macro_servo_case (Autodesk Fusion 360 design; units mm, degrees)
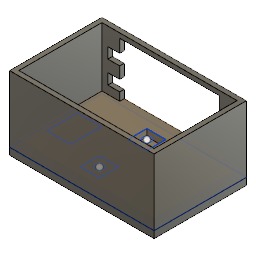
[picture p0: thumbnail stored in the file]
sketch "Sketch1" plane through (0, 0, 0) normal (0, 1, 0) x axis (1, 0, 0)
  line L1 (36.1323, 27.0695) -> (-24.8677, 27.0695)
  line L2 (36.1323, -11.9305) -> (36.1323, 27.0695)
  line L3 (-24.8677, -11.9305) -> (36.1323, -11.9305)
  line L4 (-24.8677, 27.0695) -> (-24.8677, -11.9305)
  point P2 (-24.8677, 27.0695)
  point P3 (36.1323, 27.0695)
  point P5 (-24.8677, -11.9305)
  dimension "d1" distance P2 P3 = 61
  dimension "d2" distance P2 P5 = 39
extrude "Extrude3" new body sketch "Sketch1" against normal blind 3
extrude "Extrude1" new body sketch "Sketch1" along normal blind 28
sketch "Sketch2" plane through (0, 28, 0) normal (0, 1, 0) x axis (-1, 0, 0)
  line L1 (-36.1323, 11.9305) -> (24.8677, 11.9305)
  line L2 (-36.1323, -27.0695) -> (-36.1323, 11.9305)
  line L3 (24.8677, -27.0695) -> (-36.1323, -27.0695)
  line L4 (24.8677, 11.9305) -> (24.8677, -27.0695)
  line L5 (-34.1323, -25.0695) -> (22.8677, -25.0695)
  line L6 (-34.1323, 9.9305) -> (-34.1323, -25.0695)
  line L7 (22.8677, 9.9305) -> (-34.1323, 9.9305)
  line L8 (22.8677, -25.0695) -> (22.8677, 9.9305)
  point P6 (22.8677, -25.0695)
  point P7 (-34.1323, -25.0695)
  point P9 (22.8677, 9.9305)
  dimension "d5" distance P6 P7 = 57
  dimension "d6" distance P6 P9 = 35
  dimension "d7" distance L2 L6 = 2
  dimension "d8" distance L1 L7 = 2
extrude "Extrude2" cut sketch "Sketch2" profile of L5 L6 L7 L8 against normal blind 25
sketch "Sketch3" plane through (0, 0, -25.0695) normal (0, 0, 1) x axis (1, 0, 0)
  line L1 (-22.8677, 28) -> (34.1323, 28)
  line L2 (-22.8677, 3) -> (-22.8677, 28)
  line L3 (34.1323, 3) -> (-22.8677, 3)
  line L4 (34.1323, 28) -> (34.1323, 3)
  line L5 (-15.3677, 3) -> (-15.3677, 26)
  line L6 (26.6323, 3) -> (26.6323, 26)
  line L7 (26.6323, 26) -> (-15.3677, 26)
  line L8 (26.6323, 3) -> (-15.3677, 3)
  dimension "d13" distance L2 L4 = 57
  dimension "d19" distance L1 L7 = 2
extrude "Extrude4" cut sketch "Sketch3" profile of L3 L5 L6 L7 L8 against normal blind 3
sketch "Sketch4" plane through (0, 0, -27.0695) normal (0, 0, -1) x axis (-1, 0, 0)
  line L1 (-26.6323, 3) -> (15.3677, 3)
  line L2 (-26.6323, 26) -> (-26.6323, 3)
  line L3 (15.3677, 26) -> (-26.6323, 26)
  line L4 (15.3677, 3) -> (15.3677, 26)
  line L5 (24.8677, 0) -> (-36.1323, 0)
  line L6 (24.8677, 28) -> (24.8677, 0)
  line L7 (-36.1323, 28) -> (24.8677, 28)
  line L8 (-36.1323, 0) -> (-36.1323, 28)
  line L9 (-31.6323, 6) -> (-26.6323, 6)
  line L10 (-31.6323, 10.5) -> (-31.6323, 6)
  line L11 (-26.6323, 10.5) -> (-31.6323, 10.5)
  line L12 (-26.6323, 6) -> (-26.6323, 10.5)
  line L13 (-31.6323, 15.5) -> (-26.6323, 15.5)
  line L14 (-31.6323, 20) -> (-31.6323, 15.5)
  line L15 (-26.6323, 20) -> (-31.6323, 20)
  line L16 (-26.6323, 15.5) -> (-26.6323, 20)
  line L17 (20.3677, 10.9294) -> (15.3677, 10.9294)
  line L18 (20.3677, 6.4294) -> (20.3677, 10.9294)
  line L19 (15.3677, 6.4294) -> (20.3677, 6.4294)
  line L20 (15.3677, 10.9294) -> (15.3677, 6.4294)
  line L21 (20.3677, 20.4294) -> (15.3677, 20.4294)
  line L22 (20.3677, 15.9294) -> (20.3677, 20.4294)
  line L23 (15.3677, 15.9294) -> (20.3677, 15.9294)
  line L24 (15.3677, 20.4294) -> (15.3677, 15.9294)
  point P10 (-26.6323, 6)
  point P13 (-26.6323, 10.5)
  dimension "d22" distance P10 P13 = 4.5
  dimension "d23" distance L1 L9 = 3
  dimension "d6" = 35
  dimension "d25" distance L10 L12 = 5
  dimension "d26" distance L14 L16 = 5
  dimension "d27" distance L11 L13 = 5
  dimension "d46" distance L17 L19 = 4.5
  dimension "d47" distance L21 L23 = 4.5
  dimension "d48" distance L17 L23 = 5
  dimension "d24" distance = 4.5
extrude "Extrude5" cut sketch "Sketch4" profile of L2 L4 L9 L10 L11 L12 L13 L14 L15 L16 L17 L18 L19 L20 L21 L22 L23 L24 against normal blind 4
sketch "Sketch5" plane through (0, 3, 0) normal (0, 1, 0) x axis (-1, 0, 0)
  line L1 (-34.1323, 9.9305) -> (22.8677, 9.9305)
  line L2 (-34.1323, -25.0695) -> (-34.1323, 9.9305)
  line L3 (-26.6323, -25.0695) -> (-34.1323, -25.0695)
  line L4 (-26.6323, -27.0695) -> (-26.6323, -25.0695)
  line L5 (15.3677, -27.0695) -> (-26.6323, -27.0695)
  line L6 (15.3677, -25.0695) -> (15.3677, -27.0695)
  line L7 (22.8677, -25.0695) -> (15.3677, -25.0695)
  line L8 (22.8677, 9.9305) -> (22.8677, -25.0695)
  line L9 (-8.3432, -0.8325) -> (-0.3432, -0.8325)
  line L10 (-8.3432, -12.8325) -> (-8.3432, -20.8325)
  line L11 (-8.3432, 7.1675) -> (-8.3432, -0.8325)
  line L12 (-0.3432, 7.1675) -> (-8.3432, 7.1675)
  line L13 (-0.3432, -0.8325) -> (-0.3432, 7.1675)
  line L14 (-8.3432, -20.8325) -> (-0.3432, -20.8325)
  line L15 (-0.3432, -12.8325) -> (-8.3432, -12.8325)
  line L16 (-0.3432, -20.8325) -> (-0.3432, -12.8325)
  line L17 (10, -12) -> (20, -12)
  line L18 (10, 1) -> (10, -12)
  line L19 (20, 1) -> (10, 1)
  line L20 (20, -12) -> (20, 1)
  circle C1 centre (-4.3432, 3.1675) radius 1.75
  circle C2 centre (-4.3432, -16.8325) radius 1.75
  point P10 (-0.3432, -0.8325)
  point P19 (-8.3432, -0.8325)
  point P11 (-4.3432, 3.1675)
  point P18 (-4.3432, -16.8325)
  dimension "d35" distance P10 P19 = 8
  dimension "d36" diameter C2 = 3.5
  dimension "d37" diameter C1 = 3.5
  dimension "d38" distance P11 P18 = 20
  dimension "d39" distance L9 L12 = 8
  dimension "d40" distance L9 L14 = 20
  dimension "d41" distance P18 L14 = 4
  dimension "d49" distance L18 L20 = 10
  dimension "d50" distance L17 L19 = 13
extrude "Extrude8" cut sketch "Sketch5" profile of L17 L18 L19 L20 against normal blind 13
extrude "Extrude7" cut sketch "Sketch5" profile of C1 C2 against normal blind 10
extrude "Extrude6" cut sketch "Sketch5" profile of L9 C1 C2 L10 L11 L12 L13 L14 L15 L16 against normal blind 3
thread "Thread1"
